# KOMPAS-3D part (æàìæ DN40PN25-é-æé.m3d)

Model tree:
1. Объединить компоненты:1  (labels: СЕНС DN40PN25-В)
2. Эскиз:1
3. Операция выдавливания:1
     Расстояние 1 = 14
4. Фаска:1
     Угол = 45; Длина 1 = 2; Длина 2 = 2

Referenced files in D:\Савин\!СЕНСОР\3D для заказчика\!Новый перечень\СЕНС\3. СЕНС-В\DN40\: СЕНС DN40PN25-В.a3d
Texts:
  СЕНС DN40PN25-В-СВ
  ООО НПП Сенсор
  СЕНС DN40PN25-В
